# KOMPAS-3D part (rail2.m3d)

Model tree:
1. X Axis
2. Y Axis
3. Z Axis
4. Origin  (labels: rail2; D:\Program Files\ASCON\KOMPAS-3D V10\Sys\GRAPHIC_EN.LYT; Rail 02)
     Wall Thickness 1 = 1; Wall Thickness 2 = 1; Distance 1 = 50; Distance 2 = 10

Referenced files in D:\Documents and Settings\kashirsky\Рабочий стол\My sample\: Side plate.a3d
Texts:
  Rail 02
  rail2
  Three Point Plane
  Plane at Angle
  Line and Point Plane
  Axis through Two Vertices
  Axis of Feature
  Axis of Conical Surface
  Axis through Edge
  Trim by Surface
  Trim by Sketch
  Feature with No History
  Intersection Axis of Two Planes
  Two Line Plane
  Line and Face Plane
  Bend by line
  Hole in sheet body
  Cut in sheet body
  Point in CM
  Linear Dimension from Line to Point
  Surface Finish Symbol
  Geometric Tolerance Symbol
  Leader #1
  Leader #2
  Leader #3
  Shape Deviations and Datum
  Node point number
  Mark of coordination axis
  Node point designation
  Mark/Reference designation with leader
  Mark/reference designation on line
  Mark/Reference designation without leader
